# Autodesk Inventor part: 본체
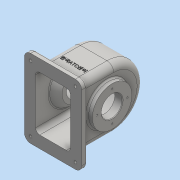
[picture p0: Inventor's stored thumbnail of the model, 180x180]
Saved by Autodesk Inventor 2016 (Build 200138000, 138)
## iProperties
Created: 2018-11
Part Number: 본체
Material: 일반
Document SubType Name: Modeling
Designer: user
Density: 1 g/cm^3
Appearance: 기본값
Author: user
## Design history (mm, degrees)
sketch "스케치1"
  geometry: L1 (-55, -75)-(55, -75); L2 (55, -75)-(55, 75); L3 (55, 75)-(-55, 75); L4 (-55, 75)-(-55, -75); L5 (-55, -75)-(55, 75); L6 (55, -75)-(-55, 75); 1 further point
  constraints: 12 end point, 2 midpoint, 2 parallel, 1 horizontal, 1 perpendicular
  dimensions: "d0" = 110 distance of L3.end L2.end; "d1" = 150 distance of L1.end L2.end
extrude "돌출1" new body sketch "스케치1" distance "d2" = 10; taper "d3" = 0 deg
sketch "스케치2"
  geometry: L1 (-38.5, 58)-(38.5, 58); L2 (38.5, 58)-(38.5, -58); L3 (38.5, -58)-(-38.5, -58); L4 (-38.5, -58)-(-38.5, 58); L5 (-38.5, 58)-(38.5, -58); L6 (38.5, 58)-(-38.5, -58); 1 further point
  constraints: 12 end point, 2 midpoint, 2 parallel, 1 horizontal, 1 perpendicular
  dimensions: "d4" = 77 distance of L2.end L3.end; "d5" = 116 distance of L1.end L2.end
extrude "돌출2" join sketch "스케치2" distance "d6" = 126; taper "d7" = 0 deg
fillet "모깎기1" dims "d8" = 58
feature "쉘1" dims "d13" = 6, "d14" = 5, "d15" = 10
sketch "스케치5"
  geometry: L1 (-17, -10)-(133, -10) reference; C1 r 38 at (58, 55); 2 further points
  constraints: 1 centre point, 1 midpoint, 1 vertical alignment
  dimensions: "d16" = 76 diameter of C1; "d17" = 65 distance from line of C1.centre L1
extrude "돌출4" join sketch "스케치5" distance "d18" = 10; taper "d19" = 0 deg
sketch "스케치6"
  geometry: L1 (-17, -10)-(133, -10) reference; C1 r 38 at (58, 55); 2 further points
  constraints: 1 centre point, 1 midpoint, 1 vertical alignment
  dimensions: "d20" = 76 diameter of C1; "d21" = 65 distance from line of L1 C1.centre
extrude "돌출5" join sketch "스케치6" distance "d22" = 5; taper "d23" = 0 deg
node "작업 평면1"
sketch "스케치7"
  geometry: C1 r 6 at (0, 0); 1 further point
  constraints: 1 centre point, 1 coincident
  dimensions: "d25" = 12 diameter of C1
extrude "돌출6" join sketch "스케치7" stored distance "d26" = 5; taper "d27" = 5 deg
sketch "스케치8"
  geometry: 2 further points
  constraints: 1 coincident
hole "구멍1" sketch "스케치8" at (0, 0) diameter "d28" = 4.459; stored, may be unused: countersink angle "d32" = 90 deg, drill point angle "d34" = 118 deg; dims "d29" = 20, "d30" = 4, "d31" = 2, "d33" = 12.8
node "작업 평면2"
sketch "스케치10"
  geometry: C1 r 28 at (0, 0); 1 further point
  constraints: 1 centre point, 1 vertical alignment
  dimensions: "d36" = 56 diameter of C1; "d37" = 65 distance of C1.centre point (0, -65)
extrude "돌출7" join sketch "스케치10" stored distance "d38" = 5; taper "d39" = 40 deg
sketch "스케치11"
  geometry: L1 (-75, -65)-(75, -65) reference; C1 r 20 at (0, 0); 2 further points
  constraints: 1 centre point, 1 midpoint, 1 vertical alignment
  dimensions: "d40" = 40 diameter of C1; "d41" = 65 distance from line of C1.centre L1
extrude "돌출8" cut sketch "스케치11" stored distance "d42" = 5; taper "d43" = 0 deg
sketch "스케치12"
  geometry: L1 (-75, -65)-(75, -65) reference; C1 r 20 at (0, 0) reference; 3 further points
  constraints: 1 midpoint, 1 vertical alignment
  dimensions: "d44" = 29 distance of point (0, 29) C1.centre
hole "구멍2" sketch "스케치12" at (0, 29) diameter "d45" = 3.242; stored, may be unused: countersink angle "d49" = 90 deg, drill point angle "d51" = 118 deg; dims "d46" = 8, "d47" = 4, "d48" = 2, "d50" = 10
sketch "스케치13"
  geometry: C1 r 20 at (0, 0) reference; 2 further points
  constraints: 1 vertical alignment
  dimensions: "d55" = 29 distance of C1.centre point (0, 29)
hole "구멍3" sketch "스케치13" at (0, 29) diameter "d56" = 3.242; stored, may be unused: countersink angle "d60" = 90 deg, drill point angle "d62" = 118 deg; dims "d57" = 8, "d58" = 4, "d59" = 2, "d61" = 10
fillet "모깎기2" dims "d66" = 12
sketch "스케치14"
  geometry: A1 r 12 centre (43, -63) between (43, -75) and (55, -63) reference; A2 r 12 centre (-43, -63) between (-55, -63) and (-43, -75) reference; A3 r 12 centre (43, 63) between (55, 63) and (43, 75) reference; A4 r 12 centre (-43, 63) between (-43, 75) and (-55, 63) reference; 1 further point
hole "구멍4" sketch "스케치14" at (43, -63), (-43, -63), (43, 63), (-43, 63) diameter "d67" = 5; stored, may be unused: countersink angle "d71" = 90 deg, drill point angle "d73" = 0 deg; dims "d68" = 8, "d69" = 12, "d70" = 4, "d72" = 10
fillet "모깎기3" dims "d74" = 13
fillet "모깎기4" dims "d75" = 3
fillet "모깎기5" dims "d76" = 8
fillet "모깎기6" dims "d77" = 3
sketch "스케치15"
  geometry: L1 (-17.5, -78)-(-29.5, -78) reference; L2 (-13, 0)-(-13, -65) reference; 2 further points
  constraints: 1 other
  dimensions: "d78" = 40 distance from line of point (25.5, -38) L1; "d79" = 38.5 distance from line of point (25.5, -38) L2
feature "엠보싱1" sketch "스케치15" dims "d0" = 110, "d1" = 150, "d80" = 0.5, "d81" = 0
chamfer "모따기1" distance "d82" = 1; stored, may be unused: second distance "d83" = 2, angle "d84" = 45 deg
fillet "모깎기7" dims "d85" = 3
sketch "스케치3"
  geometry: L1 (-17, -10)-(133, -10) reference; C1 r 38 at (58, 55); 2 further points
  constraints: 1 centre point, 1 midpoint, 1 vertical alignment
  dimensions: "d9" = 76 diameter of C1; "d10" = 65 distance from line of C1.centre L1
extrude "돌출3" join sketch "스케치3" distance "d11" = 10; taper "d12" = 0 deg
node "솔리드1"
pattern_circular "원형 패턴1" dims angle "d53" = 360 deg
pattern_circular "원형 패턴2" dims angle "d64" = 360 deg
other parameters: "d24" = 142, "d35" = -24
